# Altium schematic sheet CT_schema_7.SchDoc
size 387 x 379 mm
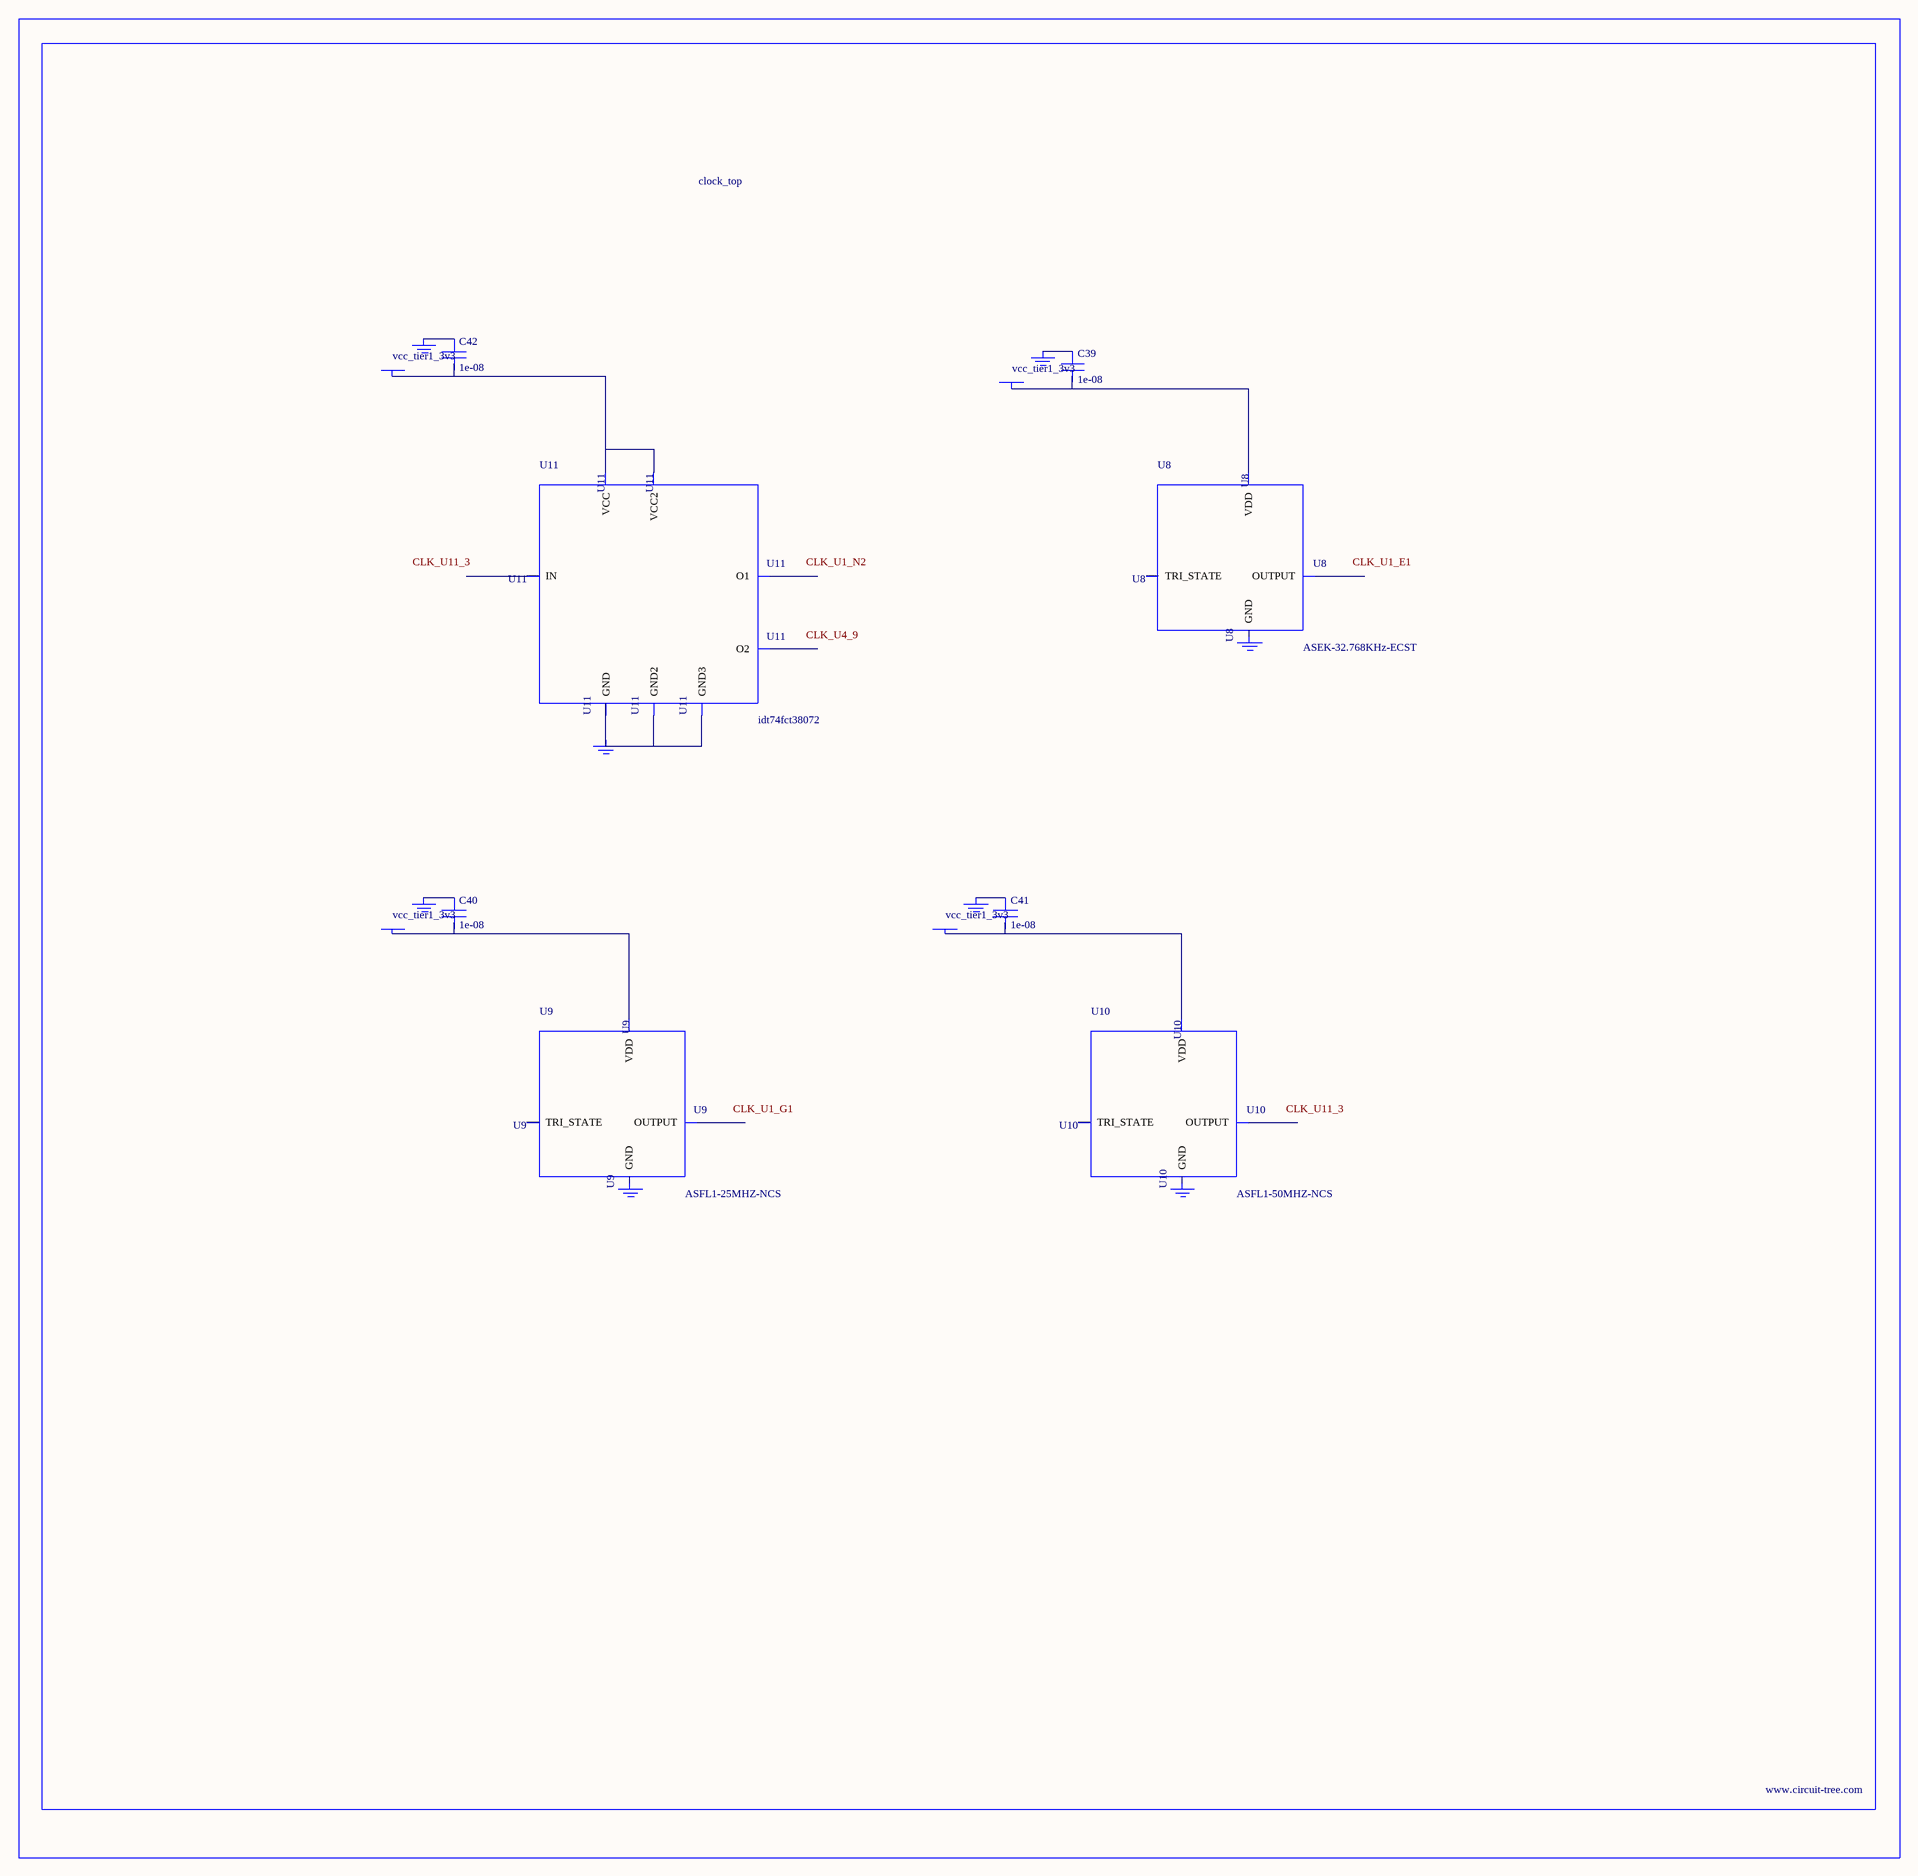
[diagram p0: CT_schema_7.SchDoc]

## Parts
BORDER6  (no value)
C39  1e-08  [C0402]
C40  1e-08  [C0402]
C41  1e-08  [C0402]
C42  1e-08  [C0402]
GND_INSTANCE_6_0  (no value)
GND_INSTANCE_6_1  (no value)
GND_INSTANCE_6_2  (no value)
GND_INSTANCE_6_3  (no value)
GND_INSTANCE_6_4  (no value)
GND_INSTANCE_6_5  (no value)
GND_INSTANCE_6_6  (no value)
GND_INSTANCE_6_7  (no value)
POWER_INSTANCE_6_0  vcc_tier1_3v3
POWER_INSTANCE_6_1  vcc_tier1_3v3
POWER_INSTANCE_6_2  vcc_tier1_3v3
POWER_INSTANCE_6_3  vcc_tier1_3v3
U8  ASEK-32.768KHz-ECST  [ASEK]
U9  ASFL1-25MHZ-NCS  [ASFL1]
U10  ASFL1-50MHZ-NCS  [ASFL1]
U11  idt74fct38072  [IDT74FCT38072]

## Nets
NetC39_1: C39.1 GND_INSTANCE_6_0.0(GND)
NetC39_2: C39.2 POWER_INSTANCE_6_0.0(PWR) U8.4(VDD)
NetC40_1: C40.1 GND_INSTANCE_6_2.0(GND)
NetC40_2: C40.2 POWER_INSTANCE_6_1.0(PWR) U9.4(VDD)
NetC41_1: C41.1 GND_INSTANCE_6_4.0(GND)
NetC41_2: C41.2 POWER_INSTANCE_6_2.0(PWR) U10.4(VDD)
NetC42_1: C42.1 GND_INSTANCE_6_6.0(GND)
NetC42_2: C42.2 POWER_INSTANCE_6_3.0(PWR) U11.1(VCC) U11.2(VCC2)
NetGND_INSTANCE_6_7_0: GND_INSTANCE_6_7.0(GND) U11.4(GND) U11.5(GND2) U11.8(GND3)

Not connected (* = marked no-connect by the designer): GND_INSTANCE_6_1 0(GND); GND_INSTANCE_6_3 0(GND); GND_INSTANCE_6_5 0(GND); U8 1(TRI_STATE) 2(GND) 3(OUTPUT); U9 1(TRI_STATE) 2(GND) 3(OUTPUT); U10 1(TRI_STATE) 2(GND) 3(OUTPUT); U11 3(IN) 6(O2) 7(O1)

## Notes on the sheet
- Labels drawn without touching a wire or pin: CLK_U1_E1, CLK_U1_G1, CLK_U1_N2, CLK_U4_9, CLK_U11_3

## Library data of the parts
BORDER6 = BORDER_PAGE6
C39-C42 = C0402C103K3RAC
GND_INSTANCE_6_0-GND_INSTANCE_6_7 = GND
POWER_INSTANCE_6_0-POWER_INSTANCE_6_3 = PWR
